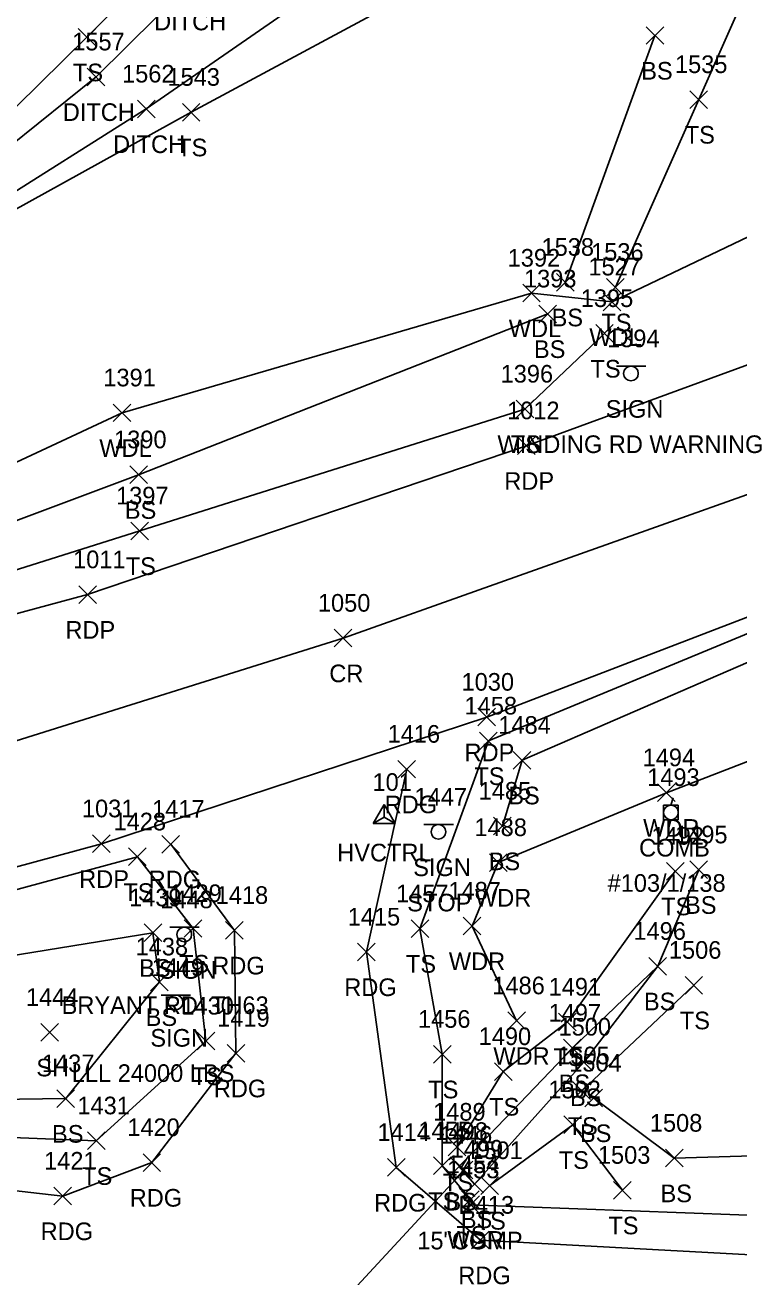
# Model space of a CAD drawing. Extents: x 1633660 to 1636532, y 388643 to 392631.
# Drawn here: x 1634075.1 to 1634156, y 388733.9 to 388875.9 of the extents above; entities that cross this region are included whole.
import ezdxf

# ---------------------------------------------------------------- set-up
doc = ezdxf.new("R2010")
doc.units = 0
for name, color, linetype in [('C_A', 7, 'Continuous'), ('C_I', 7, 'Continuous'), ('CPSM', 7, 'Continuous'), ('D_A', 7, 'Continuous'), ('D_C', 7, 'Continuous'), ('D_I', 7, 'Continuous'), ('D_TIC', 7, 'Continuous'), ('DCP', 7, 'Continuous'), ('DD', 7, 'Continuous'), ('L_A', 7, 'Continuous'), ('L_I', 7, 'Continuous'), ('L_TIC', 7, 'Continuous'), ('LAWA', 7, 'Continuous'), ('LELB', 7, 'Continuous'), ('P_A', 7, 'Continuous'), ('P_I', 7, 'Continuous'), ('P_TIC', 7, 'Continuous'), ('PET', 7, 'Continuous'), ('PEU', 7, 'Continuous'), ('PRC', 7, 'Continuous'), ('S_A', 7, 'Continuous'), ('S_C', 7, 'Continuous'), ('S_I', 7, 'Continuous'), ('SSGN', 7, 'Continuous'), ('U_A', 7, 'Continuous'), ('U_C', 7, 'Continuous'), ('U_I', 7, 'Continuous'), ('UP', 7, 'Continuous')]:
    doc.layers.add(name, color=color, linetype=linetype)

msp = doc.modelspace()

# ---------------------------------------------------------------- linework, layer by layer
at = {"layer": 'CPSM'}
for p, q in [((1634114.53, 388785.32), (1634115.78, 388787.48)), ((1634117.03, 388785.32), (1634115.78, 388787.48)), ((1634115.78, 388786.04), (1634115.78, 388787.48)), ((1634114.53, 388785.32), (1634115.78, 388786.04)), ((1634115.78, 388786.04), (1634115.78, 388786.04)), ((1634115.78, 388786.04), (1634117.03, 388785.32)), ((1634114.53, 388785.32), (1634117.03, 388785.32))]:
    msp.add_line(p, q, dxfattribs=at)
at = {"layer": 'D_TIC'}
for points in [[(1634082.12, 388869.01), (1634084.12, 388871.01)], [(1634084.12, 388869.01), (1634082.12, 388871.01)], [(1634087.81, 388865.37), (1634089.81, 388867.37)], [(1634089.81, 388865.37), (1634087.81, 388867.37)], [(1634123.85, 388745.04), (1634125.85, 388747.04)], [(1634125.85, 388745.04), (1634123.85, 388747.04)]]:
    msp.add_lwpolyline(points, dxfattribs=at)
at = {"layer": 'DCP'}
msp.add_lwpolyline([(1634104.33, 388723.83), (1634124.85, 388746.04)], dxfattribs=at)
at = {"layer": 'DD'}
msp.add_lwpolyline([(1634140.31, 388919.4), (1634122.83, 388893.99), (1634093.48, 388880.29), (1634083.12, 388870.01), (1634069.93, 388859.42), (1634050.51, 388859.37), (1634048.14, 388856.2), (1634070.58, 388854.91), (1634088.81, 388866.37), (1634110.94, 388881.74), (1634127.84, 388889.81), (1634143.36, 388916.71)], dxfattribs=at)
at = {"layer": 'L_TIC'}
for points in [[(1634081.09, 388873.51), (1634083.09, 388875.51)], [(1634083.09, 388873.51), (1634081.09, 388875.51)], [(1634145.5, 388873.7), (1634147.5, 388875.7)], [(1634147.5, 388873.7), (1634145.5, 388875.7)], [(1634150.47, 388866.44), (1634152.47, 388868.44)], [(1634152.47, 388866.44), (1634150.47, 388868.44)], [(1634092.91, 388865), (1634094.91, 388867)], [(1634094.91, 388865), (1634092.91, 388867)], [(1634135.34, 388845.72), (1634137.34, 388847.72)], [(1634137.34, 388845.72), (1634135.34, 388847.72)], [(1634141.01, 388845.15), (1634143.01, 388847.15)], [(1634143.01, 388845.15), (1634141.01, 388847.15)], [(1634131.5, 388844.49), (1634133.5, 388846.49)], [(1634133.5, 388844.49), (1634131.5, 388846.49)], [(1634140.64, 388843.49), (1634142.64, 388845.49)], [(1634142.64, 388843.49), (1634140.64, 388845.49)], [(1634133.34, 388842.13), (1634135.34, 388844.13)], [(1634135.34, 388842.13), (1634133.34, 388844.13)], [(1634139.78, 388839.91), (1634141.78, 388841.91)], [(1634141.78, 388839.91), (1634139.78, 388841.91)], [(1634085.07, 388830.91), (1634087.07, 388832.91)], [(1634087.07, 388830.91), (1634085.07, 388832.91)], [(1634130.75, 388831.34), (1634132.75, 388833.34)], [(1634132.75, 388831.34), (1634130.75, 388833.34)], [(1634086.95, 388823.89), (1634088.95, 388825.89)], [(1634088.95, 388823.89), (1634086.95, 388825.89)], [(1634087.08, 388817.52), (1634089.08, 388819.52)], [(1634089.08, 388817.52), (1634087.08, 388819.52)], [(1634126.61, 388793.7), (1634128.61, 388795.7)], [(1634128.61, 388793.7), (1634126.61, 388795.7)], [(1634130.43, 388791.51), (1634132.43, 388793.51)], [(1634132.43, 388791.51), (1634130.43, 388793.51)], [(1634146.8, 388787.83), (1634148.8, 388789.83)], [(1634148.8, 388787.83), (1634146.8, 388789.83)], [(1634128.2, 388784.04), (1634130.2, 388786.04)], [(1634130.2, 388784.04), (1634128.2, 388786.04)], [(1634086.81, 388780.56), (1634088.81, 388782.56)], [(1634088.81, 388780.56), (1634086.81, 388782.56)], [(1634127.73, 388779.91), (1634129.73, 388781.91)], [(1634129.73, 388779.91), (1634127.73, 388781.91)], [(1634147.81, 388778.93), (1634149.81, 388780.93)], [(1634149.81, 388778.93), (1634147.81, 388780.93)], [(1634150.47, 388779.09), (1634152.47, 388781.09)], [(1634152.47, 388779.09), (1634150.47, 388781.09)], [(1634124.77, 388772.71), (1634126.77, 388774.71)], [(1634126.77, 388772.71), (1634124.77, 388774.71)], [(1634088.57, 388771.95), (1634090.57, 388773.95)], [(1634090.57, 388771.95), (1634088.57, 388773.95)], [(1634093.13, 388772.43), (1634095.13, 388774.43)], [(1634095.13, 388772.43), (1634093.13, 388774.43)], [(1634118.85, 388772.41), (1634120.85, 388774.41)], [(1634120.85, 388772.41), (1634118.85, 388774.41)], [(1634145.81, 388768.15), (1634147.81, 388770.15)], [(1634147.81, 388768.15), (1634145.81, 388770.15)], [(1634089.31, 388766.38), (1634091.31, 388768.38)], [(1634091.31, 388766.38), (1634089.31, 388768.38)], [(1634149.91, 388766), (1634151.91, 388768)], [(1634151.91, 388766), (1634149.91, 388768)], [(1634129.81, 388761.97), (1634131.81, 388763.97)], [(1634131.81, 388761.97), (1634129.81, 388763.97)], [(1634135.57, 388761.83), (1634137.57, 388763.83)], [(1634137.57, 388761.83), (1634135.57, 388763.83)], [(1634076.86, 388760.66), (1634078.86, 388762.66)], [(1634078.86, 388760.66), (1634076.86, 388762.66)], [(1634094.58, 388759.67), (1634096.58, 388761.67)], [(1634096.58, 388759.67), (1634094.58, 388761.67)], [(1634136.14, 388758.87), (1634138.14, 388760.87)], [(1634138.14, 388758.87), (1634136.14, 388760.87)], [(1634121.38, 388758.17), (1634123.38, 388760.17)], [(1634123.38, 388758.17), (1634121.38, 388760.17)], [(1634137.43, 388757.29), (1634139.43, 388759.29)], [(1634139.43, 388757.29), (1634137.43, 388759.29)], [(1634128.29, 388756.21), (1634130.29, 388758.21)], [(1634130.29, 388756.21), (1634128.29, 388758.21)], [(1634078.68, 388753.14), (1634080.68, 388755.14)], [(1634080.68, 388753.14), (1634078.68, 388755.14)], [(1634137.19, 388754.03), (1634139.19, 388756.03)], [(1634139.19, 388754.03), (1634137.19, 388756.03)], [(1634138.55, 388753.21), (1634140.55, 388755.21)], [(1634140.55, 388753.21), (1634138.55, 388755.21)], [(1634136.18, 388750.17), (1634138.18, 388752.17)], [(1634138.18, 388750.17), (1634136.18, 388752.17)], [(1634082.14, 388748.36), (1634084.14, 388750.36)], [(1634084.14, 388748.36), (1634082.14, 388750.36)], [(1634123.05, 388747.64), (1634125.05, 388749.64)], [(1634125.05, 388747.64), (1634123.05, 388749.64)], [(1634147.69, 388746.39), (1634149.69, 388748.39)], [(1634149.69, 388746.39), (1634147.69, 388748.39)], [(1634121.38, 388745.52), (1634123.38, 388747.52)], [(1634123.38, 388745.52), (1634121.38, 388747.52)], [(1634123.3, 388745.45), (1634125.3, 388747.45)], [(1634125.3, 388745.45), (1634123.3, 388747.45)], [(1634125.04, 388743.45), (1634127.04, 388745.45)], [(1634127.04, 388743.45), (1634125.04, 388745.45)], [(1634126.76, 388743.28), (1634128.76, 388745.28)], [(1634128.76, 388743.28), (1634126.76, 388745.28)], [(1634124.58, 388741.69), (1634126.58, 388743.69)], [(1634126.58, 388741.69), (1634124.58, 388743.69)], [(1634141.81, 388742.75), (1634143.81, 388744.75)], [(1634143.81, 388742.75), (1634141.81, 388744.75)], [(1634124.6, 388741.11), (1634126.6, 388743.11)], [(1634126.6, 388741.11), (1634124.6, 388743.11)]]:
    msp.add_lwpolyline(points, dxfattribs=at)
at = {"layer": 'LAWA'}
for points in [[(1634029.51, 388906.75), (1634042.75, 388866.2), (1634043.29, 388851.86), (1634059.73, 388819.64), (1634086.07, 388831.91), (1634132.5, 388845.49), (1634141.64, 388844.49), (1634171.78, 388858.91), (1634210.32, 388873.4), (1634220.65, 388882.43), (1634241.67, 388885.4), (1634275.37, 388895.77), (1634312.68, 388911.32), (1634346.59, 388927.34), (1634362.7, 388937.8), (1634391.49, 388949.24), (1634419.55, 388956.24), (1634431.93, 388958.02)], [(1634130.81, 388762.97), (1634125.77, 388773.71), (1634128.73, 388780.91), (1634147.8, 388788.83), (1634164.31, 388795.2), (1634191.33, 388807.23), (1634212.88, 388815.09), (1634244.47, 388827.57), (1634270.05, 388838.56), (1634299.49, 388850.56), (1634310.77, 388855.38), (1634327.21, 388862.06), (1634379.71, 388881.61), (1634402.37, 388888.88), (1634424.47, 388897.46), (1634452.16, 388917.36), (1634475.03, 388932.29), (1634483.74, 388944.66)], [(1634213.99, 388739.9), (1634162.11, 388740.72), (1634125.6, 388742.11)]]:
    msp.add_lwpolyline(points, dxfattribs=at)
at = {"layer": 'LELB'}
for points in [[(1634125.58, 388742.69), (1634122.38, 388746.52), (1634122.38, 388759.17), (1634119.85, 388773.41), (1634127.61, 388794.7), (1634159.93, 388808.1), (1634199.65, 388823.28), (1634240.01, 388839.13), (1634282.64, 388856.78), (1634322.87, 388872.9), (1634357.4, 388883.6), (1634392.97, 388895.75), (1634413.99, 388898.72), (1634440.42, 388919.1), (1634461.6, 388936.25), (1634480.46, 388947.83), (1634480.68, 388954.28)], [(1634144.21, 388912.2), (1634135.78, 388896.22), (1634121.93, 388881.1), (1634093.91, 388866), (1634071.27, 388853.48), (1634044.09, 388851.99), (1634045.65, 388862.67), (1634068.75, 388861.41), (1634082.09, 388874.51), (1634092.19, 388884.76), (1634120.03, 388895.98), (1634133.03, 388917.32)], [(1634171.15, 388905.19), (1634160.33, 388887.42), (1634151.47, 388867.44), (1634142.01, 388846.15)], [(1634136.34, 388846.72), (1634146.5, 388874.7)], [(1634339.35, 388869.85), (1634331.59, 388873.07), (1634294.07, 388857.44), (1634255.17, 388842.14), (1634212.56, 388826.33), (1634166.48, 388807.72), (1634131.43, 388792.51), (1634129.2, 388785.04)], [(1633865.46, 388809.99), (1633877.4, 388789.31), (1633913.51, 388790.13), (1633934.95, 388796.07), (1633973.78, 388798.8), (1634008.4, 388803.18), (1634057.79, 388813.56), (1634087.95, 388824.89), (1634134.34, 388843.13)], [(1634140.78, 388840.91), (1634131.75, 388832.34), (1634088.08, 388818.52), (1634045.58, 388805.1), (1633995.02, 388794.98), (1633949.56, 388789), (1633902.34, 388786.74), (1633874.08, 388786.77)], [(1634004.85, 388759.89), (1634028.39, 388766.31), (1634055.55, 388772.84), (1634087.81, 388781.56), (1634094.13, 388773.43), (1634095.58, 388760.67), (1634083.14, 388749.36), (1634045.88, 388750.81), (1634017.74, 388755.13)], [(1634124.05, 388748.64), (1634129.29, 388757.21), (1634136.57, 388762.83), (1634148.81, 388779.93)], [(1634151.47, 388780.09), (1634146.81, 388769.15), (1634137.14, 388759.87), (1634124.3, 388746.45), (1634126.04, 388744.45), (1634138.43, 388758.29)], [(1634139.55, 388754.21), (1634148.69, 388747.39), (1634177.92, 388748.25), (1634206.1, 388754.31), (1634231.04, 388759.99), (1634261.07, 388775.55)], [(1634014, 388758.42), (1634042.35, 388754.81), (1634063.87, 388753.94), (1634079.68, 388754.14), (1634090.31, 388767.38), (1634089.57, 388772.95), (1634062.3, 388768.5), (1634039.99, 388760.86)], [(1634138.43, 388758.29), (1634146.81, 388769.15)], [(1634138.19, 388755.03), (1634150.91, 388767)], [(1634127.76, 388744.28), (1634137.18, 388751.17), (1634142.81, 388743.75)]]:
    msp.add_lwpolyline(points, dxfattribs=at)
at = {"layer": 'P_TIC'}
for points in [[(1634130.93, 388827.18), (1634132.93, 388829.18)], [(1634132.93, 388827.18), (1634130.93, 388829.18)], [(1634081.16, 388810.29), (1634083.16, 388812.29)], [(1634083.16, 388810.29), (1634081.16, 388812.29)], [(1634110.14, 388805.36), (1634112.14, 388807.36)], [(1634112.14, 388805.36), (1634110.14, 388807.36)], [(1634126.42, 388796.4), (1634128.42, 388798.4)], [(1634128.42, 388796.4), (1634126.42, 388798.4)], [(1634117.36, 388790.5), (1634119.36, 388792.5)], [(1634119.36, 388790.5), (1634117.36, 388792.5)], [(1634082.73, 388782.04), (1634084.73, 388784.04)], [(1634084.73, 388782.04), (1634082.73, 388784.04)], [(1634090.6, 388781.99), (1634092.6, 388783.99)], [(1634092.6, 388781.99), (1634090.6, 388783.99)], [(1634097.82, 388772.22), (1634099.82, 388774.22)], [(1634099.82, 388772.22), (1634097.82, 388774.22)], [(1634112.78, 388769.77), (1634114.78, 388771.77)], [(1634114.78, 388769.77), (1634112.78, 388771.77)], [(1634097.99, 388758.29), (1634099.99, 388760.29)], [(1634099.99, 388758.29), (1634097.99, 388760.29)], [(1634088.45, 388745.89), (1634090.45, 388747.89)], [(1634090.45, 388745.89), (1634088.45, 388747.89)], [(1634116.16, 388745.33), (1634118.16, 388747.33)], [(1634118.16, 388745.33), (1634116.16, 388747.33)], [(1634078.35, 388742.09), (1634080.35, 388744.09)], [(1634080.35, 388742.09), (1634078.35, 388744.09)], [(1634125.71, 388737.09), (1634127.71, 388739.09)], [(1634127.71, 388737.09), (1634125.71, 388739.09)]]:
    msp.add_lwpolyline(points, dxfattribs=at)
at = {"layer": 'PET'}
for points in [[(1633681.12, 388754.49), (1633725.19, 388768.3), (1633776.36, 388776.79), (1633828.74, 388780.84), (1633883.05, 388781.87), (1633940.05, 388783.92), (1633980.78, 388788.35), (1634030.66, 388797.38), (1634082.16, 388811.29), (1634131.93, 388828.18), (1634182.59, 388846.73), (1634235.61, 388867.86)], [(1634233.66, 388838.29), (1634176.14, 388816.11), (1634127.42, 388797.4), (1634083.73, 388783.04), (1634035.91, 388770.06), (1633987.08, 388760.24), (1633936.49, 388754.34), (1633886.38, 388755.37), (1633827.16, 388754.09), (1633779.6, 388750.43), (1633734.35, 388742.35), (1633709.35, 388735.6), (1633689.74, 388728.83)]]:
    msp.add_lwpolyline(points, dxfattribs=at)
at = {"layer": 'PEU'}
for points in [[(1634214.78, 388736.17), (1634172.01, 388735.63), (1634126.71, 388738.09), (1634117.16, 388746.33), (1634113.78, 388770.77), (1634118.36, 388791.5)], [(1634091.6, 388782.99), (1634098.82, 388773.22), (1634098.99, 388759.29), (1634089.45, 388746.89), (1634079.35, 388743.09), (1634046.67, 388746.81), (1634019, 388751.5), (1633997.3, 388759.78)]]:
    msp.add_lwpolyline(points, dxfattribs=at)
at = {"layer": 'PRC'}
msp.add_lwpolyline([(1633685.21, 388740.89), (1633722.47, 388753.09), (1633765.95, 388761.74), (1633808.84, 388766.45), (1633860.63, 388768.05), (1633911.93, 388769.08), (1633965.45, 388772.58), (1634019.68, 388781.06), (1634071.37, 388793.87), (1634111.14, 388806.36), (1634160.92, 388824.06), (1634207.93, 388842.02), (1634253.71, 388860.36), (1634302.74, 388880.25), (1634347.86, 388899.14), (1634390.05, 388916.89), (1634425.6, 388933.8), (1634443.27, 388943.77), (1634464.46, 388957.57)], dxfattribs=at)
at = {"layer": 'SSGN'}
for p, q in [((1634142.13, 388837.2), (1634145.47, 388837.2)), ((1634143.78, 388836.37), (1634143.78, 388836.37)), ((1634120.3, 388785.22), (1634123.64, 388785.22)), ((1634121.95, 388784.39), (1634121.95, 388784.39)), ((1634091.48, 388773.58), (1634094.81, 388773.58)), ((1634093.13, 388772.75), (1634093.13, 388772.75)), ((1634090.49, 388765.88), (1634093.82, 388765.88)), ((1634092.14, 388765.05), (1634092.14, 388765.05))]:
    msp.add_line(p, q, dxfattribs=at)
for centre in [(1634143.78, 388836.37), (1634121.95, 388784.39), (1634093.13, 388772.75), (1634092.14, 388765.05)]:
    msp.add_circle(centre, 0.833, dxfattribs=at)
at = {"layer": 'UP'}
for p, q in [((1634147.48, 388785.76), (1634147.48, 388787.43)), ((1634147.48, 388787.43), (1634149.15, 388787.43)), ((1634148.56, 388788.26), (1634148.31, 388787.43)), ((1634149.15, 388787.43), (1634149.15, 388785.76)), ((1634148.31, 388786.59), (1634148.31, 388786.59)), ((1634149.15, 388785.76), (1634147.48, 388785.76)), ((1634148.06, 388784.93), (1634148.31, 388785.76))]:
    msp.add_line(p, q, dxfattribs=at)
msp.add_circle((1634148.31, 388786.59), 0.833, dxfattribs=at)

# ---------------------------------------------------------------- texts
at = {"layer": 'C_A'}
msp.add_text('HVCTRL', height=2, dxfattribs=at).set_placement((1634110.47, 388781.04))
at = {"layer": 'C_I'}
msp.add_text('101', height=2, dxfattribs=at).set_placement((1634114.47, 388789.04))
at = {"layer": 'D_A'}
for s, p in [('DITCH', (1634089.71, 388875.29)), ('DITCH', (1634079.35, 388865.01)), ('DITCH', (1634085.05, 388861.37)), ('P', (1634124.23, 388741.04))]:
    msp.add_text(s, height=2, dxfattribs=at).set_placement(p)
at = {"layer": 'D_C'}
msp.add_text('15"CGMP', height=2, dxfattribs=at).set_placement((1634119.55, 388737.04))
at = {"layer": 'D_I'}
for s, p in [('1557', (1634080.42, 388873.01)), ('1562', (1634086.07, 388869.37)), ('1446', (1634122.1, 388749.04))]:
    msp.add_text(s, height=2, dxfattribs=at).set_placement(p)
at = {"layer": 'L_A'}
for s, p in [('TS', (1634080.5, 388869.51)), ('BS', (1634144.94, 388869.7)), ('TS', (1634149.88, 388862.44)), ('TS', (1634092.32, 388861)), ('BS', (1634134.78, 388841.72)), ('TS', (1634140.42, 388841.15)), ('WDL', (1634129.92, 388840.49)), ('WDL', (1634139.06, 388839.49)), ('BS', (1634132.78, 388838.13)), ('TS', (1634139.19, 388835.91)), ('WDL', (1634083.49, 388826.91)), ('TS', (1634130.16, 388827.34)), ('BS', (1634086.39, 388819.89)), ('TS', (1634086.49, 388813.52)), ('TS', (1634126.02, 388789.7)), ('BS', (1634129.87, 388787.51)), ('WDR', (1634145.16, 388783.83)), ('BS', (1634127.65, 388780.04)), ('TS', (1634086.22, 388776.56)), ('WDR', (1634126.09, 388775.91)), ('TS', (1634147.21, 388774.93)), ('BS', (1634149.91, 388775.09)), ('TS', (1634092.54, 388768.43)), ('TS', (1634118.26, 388768.41)), ('WDR', (1634123.13, 388768.71)), ('BS', (1634088.01, 388767.95)), ('BS', (1634145.25, 388764.15)), ('BS', (1634088.75, 388762.38)), ('TS', (1634149.32, 388762)), ('WDR', (1634128.17, 388757.97)), ('TS', (1634134.98, 388757.83)), ('SH', (1634076.35, 388756.66)), ('TS', (1634093.99, 388755.67)), ('TS', (1634120.79, 388754.17)), ('BS', (1634135.58, 388754.87)), ('BS', (1634136.87, 388753.29)), ('TS', (1634127.7, 388752.21)), ('TS', (1634136.6, 388750.03)), ('BS', (1634078.13, 388749.14)), ('BS', (1634137.99, 388749.21)), ('TS', (1634135.59, 388746.17)), ('TS', (1634081.55, 388744.36)), ('TS', (1634122.46, 388743.64)), ('TS', (1634120.79, 388741.52)), ('BS', (1634122.74, 388741.45)), ('BS', (1634147.13, 388742.39)), ('BS', (1634124.48, 388739.45)), ('TS', (1634126.17, 388739.28)), ('TS', (1634141.22, 388738.75)), ('TS', (1634123.99, 388737.69)), ('WDR', (1634122.96, 388737.11))]:
    msp.add_text(s, height=2, dxfattribs=at).set_placement(p)
at = {"layer": 'L_I'}
for s, p in [('1535', (1634148.77, 388870.44)), ('1543', (1634091.22, 388869)), ('1538', (1634133.64, 388849.72)), ('1392', (1634129.8, 388848.49)), ('1536', (1634139.26, 388849.15)), ('1527', (1634138.95, 388847.49)), ('1393', (1634131.65, 388846.13)), ('1395', (1634138.09, 388843.91)), ('1396', (1634129, 388835.34)), ('1391', (1634083.95, 388834.91)), ('1390', (1634085.17, 388827.89)), ('1397', (1634085.39, 388821.52)), ('1458', (1634124.91, 388797.7)), ('1484', (1634128.74, 388795.51)), ('1494', (1634145.1, 388791.83)), ('1485', (1634126.51, 388788.04)), ('1428', (1634085.11, 388784.56)), ('1488', (1634126.03, 388783.91)), ('1492', (1634146.11, 388782.93)), ('1495', (1634148.78, 388783.09)), ('1439', (1634086.87, 388775.95)), ('1429', (1634091.43, 388776.43)), ('1457', (1634117.15, 388776.41)), ('1487', (1634123.08, 388776.71)), ('1496', (1634144.06, 388772.15)), ('1438', (1634087.61, 388770.38)), ('1506', (1634148.08, 388770)), ('1486', (1634128.06, 388765.97)), ('1491', (1634134.44, 388765.83)), ('1444', (1634075.17, 388764.66)), ('1430', (1634092.8, 388763.67)), ('1497', (1634134.44, 388762.87)), ('1456', (1634119.63, 388762.17)), ('1500', (1634135.57, 388761.29)), ('1490', (1634126.51, 388760.21)), ('1437', (1634076.99, 388757.14)), ('1505', (1634135.42, 388758.03)), ('1504', (1634136.78, 388757.21)), ('1502', (1634134.41, 388754.17)), ('1431', (1634081.01, 388752.36)), ('1489', (1634121.35, 388751.64)), ('1508', (1634145.92, 388750.39)), ('1455', (1634119.68, 388749.52)), ('1498', (1634121.6, 388749.45)), ('1499', (1634123.34, 388747.45)), ('1501', (1634125.56, 388747.28)), ('1454', (1634122.89, 388745.69)), ('1503', (1634140.03, 388746.75)), ('1453', (1634122.91, 388745.11))]:
    msp.add_text(s, height=2, dxfattribs=at).set_placement(p)
at = {"layer": 'P_A'}
for s, p in [('RDP', (1634129.42, 388823.18)), ('RDP', (1634079.65, 388806.29)), ('CR', (1634109.57, 388801.36)), ('RDP', (1634124.91, 388792.4)), ('RDG', (1634115.85, 388786.5)), ('RDP', (1634081.21, 388778.04)), ('RDG', (1634089.09, 388777.99)), ('RDG', (1634096.3, 388768.22)), ('RDG', (1634111.27, 388765.77)), ('RDG', (1634096.48, 388754.29)), ('RDG', (1634086.94, 388741.89)), ('RDG', (1634114.65, 388741.33)), ('RDG', (1634076.84, 388738.09)), ('RDG', (1634124.2, 388733.09))]:
    msp.add_text(s, height=2, dxfattribs=at).set_placement(p)
at = {"layer": 'P_I'}
for s, p in [('1012', (1634129.73, 388831.18)), ('1011', (1634080.52, 388814.29)), ('1050', (1634108.28, 388809.36)), ('1030', (1634124.57, 388800.4)), ('1416', (1634116.18, 388794.5)), ('1031', (1634081.52, 388786.04)), ('1417', (1634089.48, 388785.99)), ('1418', (1634096.69, 388776.22)), ('1415', (1634111.66, 388773.77)), ('1419', (1634096.86, 388762.29)), ('1420', (1634086.67, 388749.89)), ('1414', (1634115.04, 388749.33)), ('1421', (1634077.23, 388746.09)), ('1413', (1634124.58, 388741.09))]:
    msp.add_text(s, height=2, dxfattribs=at).set_placement(p)
at = {"layer": 'S_A'}
for p in [(1634140.92, 388831.35), (1634119.09, 388779.37), (1634090.26, 388767.73), (1634089.28, 388760.03)]:
    msp.add_text('SIGN', height=2, dxfattribs=at).set_placement(p)
at = {"layer": 'S_C'}
for s, p in [('WINDING RD WARNING', (1634128.64, 388827.35)), ('STOP', (1634118.41, 388775.37)), ('BRYANT RD  TH63', (1634079.22, 388763.73)), ('LLL 24000 LBS', (1634080.37, 388756.03))]:
    msp.add_text(s, height=2, dxfattribs=at).set_placement(p)
at = {"layer": 'S_I'}
for s, p in [('1394', (1634141.07, 388839.35)), ('1447', (1634119.24, 388787.37)), ('1448', (1634090.41, 388775.73)), ('1449', (1634089.42, 388768.03))]:
    msp.add_text(s, height=2, dxfattribs=at).set_placement(p)
at = {"layer": 'U_A'}
msp.add_text('COMB', height=2, dxfattribs=at).set_placement((1634144.7, 388781.59))
at = {"layer": 'U_C'}
msp.add_text('#103/1/138', height=2, dxfattribs=at).set_placement((1634141.13, 388777.59))
at = {"layer": 'U_I'}
msp.add_text('1493', height=2, dxfattribs=at).set_placement((1634145.62, 388789.59))

doc.saveas('drawing.dxf')
